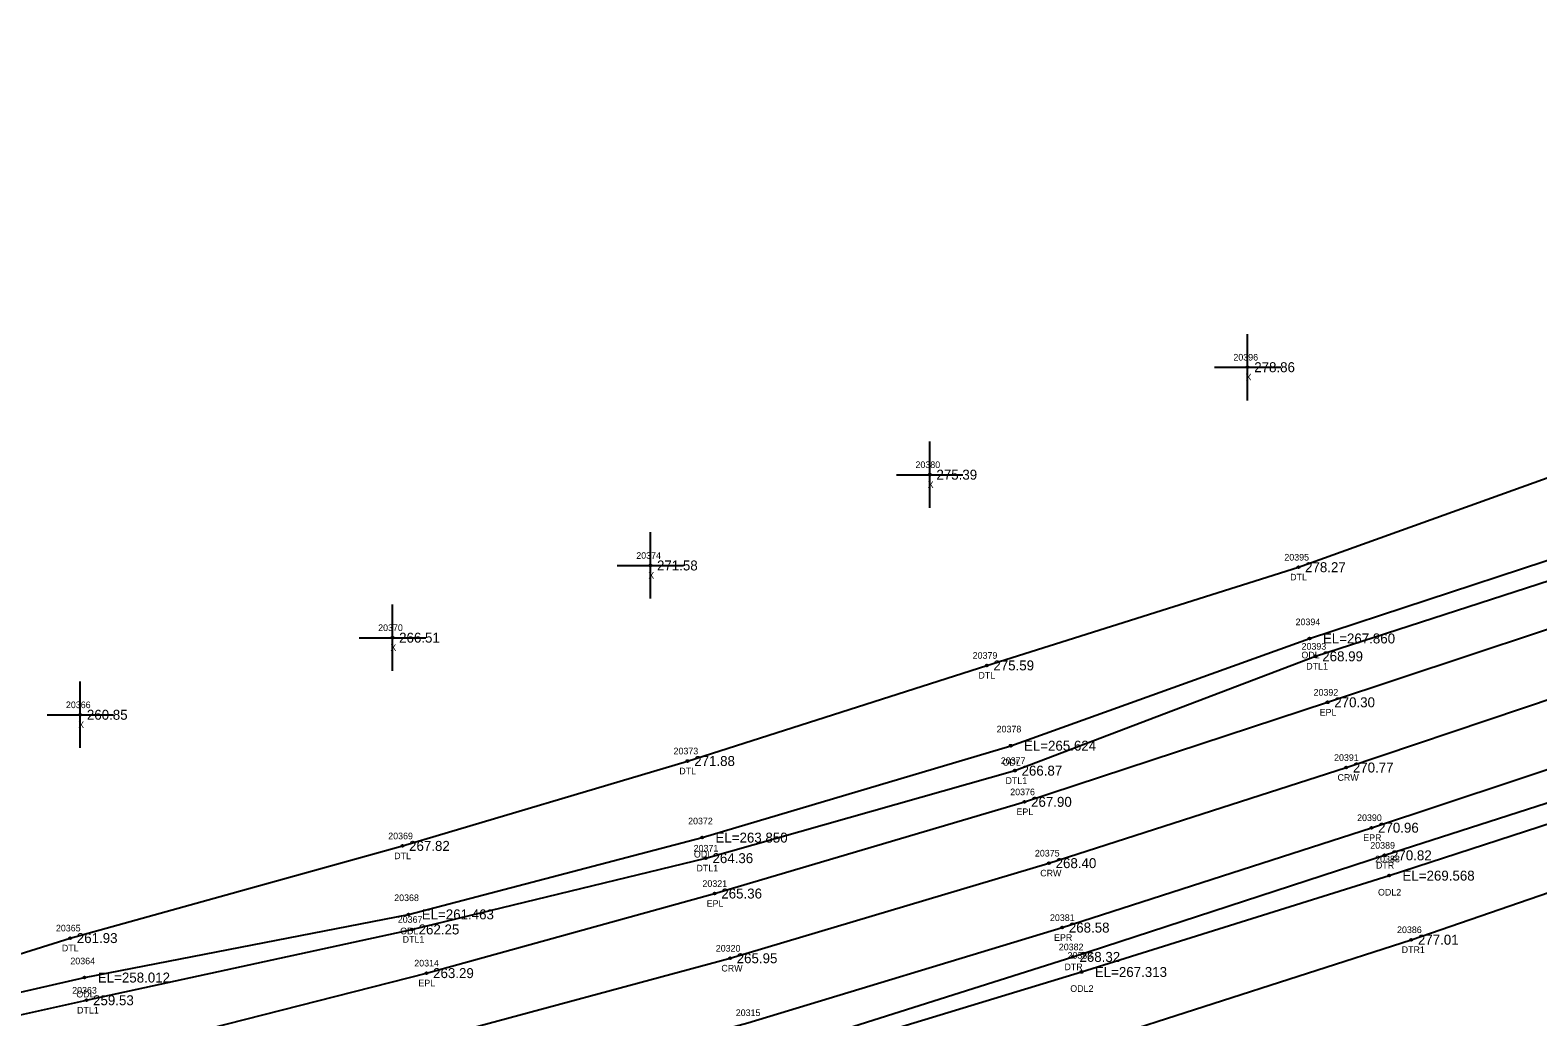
# Model space of a CAD drawing. Extents: x 2275563 to 2277161, y 1075719 to 1076412.
# Drawn here: x 2276701.4 to 2276928.6, y 1076143.1 to 1076291.8 of the extents above; entities that cross this region are included whole.
import ezdxf

# ---------------------------------------------------------------- set-up
doc = ezdxf.new("R2010")
doc.units = 0
for name, color, linetype in [('RD_DTM_BkLn1', 7, 'Continuous'), ('RD_EX_H2O', 7, 'Continuous'), ('RD_EX_H2O_txCode', 7, 'Continuous'), ('RD_EX_Misc', 7, 'Continuous'), ('RD_EX_Misc_txCode', 7, 'Continuous'), ('RD_EX_Road', 7, 'Continuous'), ('RD_EX_Road_txCode', 7, 'Continuous'), ('RD_EX_TX_H2O_ELEV', 7, 'Continuous'), ('RD_EX_TX_Misc_ELEV', 7, 'Continuous'), ('RD_EX_TX_Road_ELEV', 7, 'Continuous'), ('RD_HC_Survey_ELEV', 7, 'Continuous'), ('RD_HC_Survey_txCode', 7, 'Continuous'), ('RD_SMD_Locator', 7, 'Continuous')]:
    doc.layers.add(name, color=color, linetype=linetype)

msp = doc.modelspace()

# ---------------------------------------------------------------- linework, layer by layer
at = {"layer": 'RD_DTM_BkLn1'}
msp.add_lwpolyline([(2276380.47, 1076073.8), (2276432.36, 1076079.4), (2276487.41, 1076086.42), (2276535.62, 1076093.32), (2276578.15, 1076099.97), (2276622.03, 1076107.93), (2276668.51, 1076117.27), (2276714.2, 1076127.81), (2276762.94, 1076140.11), (2276806.88, 1076151.96), (2276854.94, 1076166.29), (2276899.73, 1076180.7), (2276952.88, 1076198.57), (2277000.46, 1076214.72), (2277057.1, 1076234.01), (2277134.93, 1076261.07)], dxfattribs=at)
at = {"layer": 'RD_EX_H2O'}
for points in [[(2276657.47, 1076152.34), (2276661.69, 1076153.68), (2276672.27, 1076150.14), (2276686.1, 1076148.32), (2276707.44, 1076155), (2276757.51, 1076168.89), (2276800.48, 1076181.68), (2276845.56, 1076196.09), (2276892.53, 1076210.89), (2276946.81, 1076230.38), (2276991.46, 1076246.85), (2277048.24, 1076266.02), (2277127.1, 1076291.82)], [(2276657.47, 1076152.34), (2276674.36, 1076145.77), (2276686.08, 1076143.69), (2276709.61, 1076149.05), (2276758.42, 1076158.57), (2276802.68, 1076170.14), (2276849.17, 1076183.99), (2276894.22, 1076200.15), (2276947.41, 1076217.63), (2276994.62, 1076234.82), (2277050.9, 1076254.6), (2277129.78, 1076281.89)], [(2276657.47, 1076152.34), (2276660.53, 1076148.68), (2276675.37, 1076140.15), (2276685.9, 1076140.33), (2276709.89, 1076145.63), (2276758.95, 1076156.3), (2276803.23, 1076167.04), (2276849.8, 1076180.23), (2276895.12, 1076197.46), (2276948.16, 1076214.68), (2276995.02, 1076232.39), (2277051.22, 1076251.9), (2277130.41, 1076279.08)], [(2276577.32, 1076064.99), (2276581.11, 1076068.71), (2276607.06, 1076074.47), (2276628.35, 1076084.13), (2276659.02, 1076095.85), (2276671.39, 1076099.39), (2276718.28, 1076111.88), (2276766.76, 1076124.15), (2276811.4, 1076137.27), (2276858.53, 1076152.16), (2276905.48, 1076167.47), (2276958.61, 1076184.59), (2277007.29, 1076200.4), (2277063.09, 1076219.53), (2277141.85, 1076245.35)], [(2276577.32, 1076064.99), (2276608.07, 1076069.56), (2276629.89, 1076080.39), (2276660.01, 1076094.12), (2276672.11, 1076097.43), (2276718.92, 1076109.66), (2276767.33, 1076122.4), (2276812.13, 1076135.39), (2276859.85, 1076149.89), (2276906.21, 1076164.41), (2276959.66, 1076181.81), (2277008.45, 1076198), (2277064.73, 1076216.97), (2277142.57, 1076243.16)], [(2276577.32, 1076064.99), (2276585.61, 1076060.77), (2276608.72, 1076065.79), (2276630.67, 1076076.21), (2276642.12, 1076079.44), (2276661.39, 1076087.16), (2276674.74, 1076089.6), (2276720.85, 1076101.92), (2276769.56, 1076115.83), (2276815.16, 1076127.06), (2276862.66, 1076139.65), (2276909.53, 1076154.75), (2276961.42, 1076172.61), (2277010.89, 1076191.18), (2277066.25, 1076211.87), (2277143.49, 1076241.1)]]:
    msp.add_lwpolyline(points, dxfattribs=at)
at = {"layer": 'RD_EX_Misc'}
for p, q in [((2276884.87, 1076236.03), (2276884.87, 1076246.03)), ((2276879.87, 1076241.03), (2276889.87, 1076241.03)), ((2276836.98, 1076219.83), (2276836.98, 1076229.83)), ((2276831.98, 1076224.83), (2276841.98, 1076224.83)), ((2276794.87, 1076206.15), (2276794.87, 1076216.15)), ((2276789.87, 1076211.15), (2276799.87, 1076211.15)), ((2276756.01, 1076195.27), (2276756.01, 1076205.27)), ((2276751.01, 1076200.27), (2276761.01, 1076200.27)), ((2276708.96, 1076183.65), (2276708.96, 1076193.65)), ((2276703.96, 1076188.65), (2276713.96, 1076188.65))]:
    msp.add_line(p, q, dxfattribs=at)
at = {"layer": 'RD_EX_Road'}
for points in [[(2276379.21, 1076084.39), (2276432.25, 1076089.28), (2276486.22, 1076095.98), (2276535.61, 1076103.32), (2276577.16, 1076110.11), (2276620.86, 1076117.78), (2276666.21, 1076126.9), (2276712, 1076137.22), (2276761.13, 1076149.72), (2276804.56, 1076161.71), (2276851.24, 1076175.53), (2276896.93, 1076190.53), (2276950.19, 1076208.22), (2276997.45, 1076224.3), (2277053.81, 1076243.77), (2277132.14, 1076270.77)], [(2276381.27, 1076063.04), (2276433.15, 1076069.16), (2276488.59, 1076076.23), (2276537.45, 1076083.34), (2276579.64, 1076090.09), (2276624.07, 1076098.24), (2276670.54, 1076107.46), (2276716.67, 1076118.09), (2276765.18, 1076130.28), (2276809.58, 1076142.25), (2276856.93, 1076156.58), (2276903.53, 1076171.63), (2276957.27, 1076189.46), (2277005.85, 1076206.01), (2277060.98, 1076225.07), (2277139.5, 1076252.36)]]:
    msp.add_lwpolyline(points, dxfattribs=at)
at = {"layer": 'RD_SMD_Locator'}
for centre in [(2276884.87, 1076241.03), (2276836.98, 1076224.83), (2276794.87, 1076211.15), (2276892.53, 1076210.89), (2276756.01, 1076200.27), (2276894.22, 1076200.15), (2276895.12, 1076197.46), (2276845.56, 1076196.09), (2276896.93, 1076190.53), (2276708.96, 1076188.65), (2276849.17, 1076183.99), (2276800.48, 1076181.68), (2276849.8, 1076180.23), (2276899.73, 1076180.7), (2276851.24, 1076175.53), (2276903.53, 1076171.63), (2276757.51, 1076168.89), (2276802.68, 1076170.14), (2276803.23, 1076167.04), (2276905.48, 1076167.47), (2276854.94, 1076166.29), (2276906.21, 1076164.41), (2276804.56, 1076161.71), (2276758.42, 1076158.57), (2276758.95, 1076156.3), (2276856.93, 1076156.58), (2276707.44, 1076155), (2276909.53, 1076154.75), (2276806.88, 1076151.96), (2276858.53, 1076152.16), (2276709.61, 1076149.05), (2276761.13, 1076149.72), (2276859.85, 1076149.89), (2276709.89, 1076145.63)]:
    msp.add_circle(centre, 0.15, dxfattribs=at)

# ---------------------------------------------------------------- texts
at = {"layer": 'RD_EX_H2O_txCode'}
for s, p in [('20395', (2276890.41, 1076211.89)), ('DTL', (2276891.28, 1076208.89)), ('20394', (2276892.1, 1076202.15)), ('20393', (2276893, 1076198.46)), ('20379', (2276843.44, 1076197.09)), ('ODL', (2276892.98, 1076197.15)), ('DTL1', (2276893.71, 1076195.46)), ('DTL', (2276844.31, 1076194.09)), ('20378', (2276847.05, 1076185.99)), ('20373', (2276798.36, 1076182.68)), ('DTL', (2276799.23, 1076179.68)), ('20377', (2276847.68, 1076181.23)), ('ODL', (2276847.93, 1076180.99)), ('DTL1', (2276848.39, 1076178.23)), ('20372', (2276800.56, 1076172.14)), ('20369', (2276755.37, 1076169.89)), ('20371', (2276801.39, 1076168.04)), ('20389', (2276903.36, 1076168.47)), ('DTL', (2276756.27, 1076166.89)), ('ODL', (2276801.43, 1076167.14)), ('20388', (2276904.09, 1076166.41)), ('DTL1', (2276801.82, 1076165.04)), ('DTR', (2276904.21, 1076165.47)), ('ODL2', (2276904.52, 1076161.41)), ('20368', (2276756.27, 1076160.57)), ('20367', (2276756.81, 1076157.3)), ('20365', (2276705.29, 1076156)), ('ODL', (2276757.17, 1076155.57)), ('20386', (2276907.39, 1076155.75)), ('DTL', (2276706.19, 1076153)), ('DTL1', (2276757.54, 1076154.3)), ('20382', (2276856.42, 1076153.16)), ('DTR1', (2276908.09, 1076152.75)), ('20364', (2276707.47, 1076151.05)), ('DTR', (2276857.27, 1076150.16)), ('20383', (2276857.73, 1076151.89)), ('20363', (2276707.74, 1076146.63)), ('ODL', (2276708.37, 1076146.05)), ('ODL2', (2276858.15, 1076146.89)), ('DTL1', (2276708.48, 1076143.63))]:
    msp.add_text(s, height=1, dxfattribs=at).set_placement(p)
at = {"layer": 'RD_EX_Misc_txCode'}
for s, p in [('20396', (2276882.73, 1076242.03)), ('X', (2276884.56, 1076239.03)), ('20380', (2276834.82, 1076225.83)), ('X', (2276836.66, 1076222.83)), ('20374', (2276792.75, 1076212.15)), ('X', (2276794.56, 1076209.15)), ('20370', (2276753.85, 1076201.27)), ('X', (2276755.69, 1076198.27)), ('20366', (2276706.8, 1076189.65)), ('X', (2276708.65, 1076186.65))]:
    msp.add_text(s, height=1, dxfattribs=at).set_placement(p)
at = {"layer": 'RD_EX_Road_txCode'}
for s, p in [('20392', (2276894.81, 1076191.53)), ('EPL', (2276895.73, 1076188.53)), ('20376', (2276849.1, 1076176.53)), ('EPL', (2276850.04, 1076173.53)), ('20390', (2276901.37, 1076172.63)), ('EPR', (2276902.3, 1076169.63)), ('20321', (2276802.72, 1076162.71)), ('EPL', (2276803.35, 1076159.71)), ('20381', (2276855.09, 1076157.58)), ('EPR', (2276855.7, 1076154.58)), ('20314', (2276759.29, 1076150.72)), ('EPL', (2276759.92, 1076147.72)), ('20315', (2276807.74, 1076143.25))]:
    msp.add_text(s, height=1, dxfattribs=at).set_placement(p)
at = {"layer": 'RD_EX_TX_H2O_ELEV'}
for s, p in [('278.27', (2276893.53, 1076210.14)), ('EL=267.860', (2276896.22, 1076199.4)), ('275.59', (2276846.56, 1076195.34)), ('268.99', (2276896.12, 1076196.71)), ('EL=265.624', (2276851.17, 1076183.24)), ('271.88', (2276801.48, 1076180.93)), ('266.87', (2276850.8, 1076179.48)), ('267.82', (2276758.51, 1076168.14)), ('EL=263.850', (2276804.68, 1076169.39)), ('264.36', (2276804.23, 1076166.29)), ('270.82', (2276906.48, 1076166.72)), ('EL=269.568', (2276908.21, 1076163.66)), ('EL=261.463', (2276760.42, 1076157.82)), ('261.93', (2276708.44, 1076154.25)), ('262.25', (2276759.95, 1076155.55)), ('277.01', (2276910.53, 1076154)), ('268.32', (2276859.53, 1076151.41)), ('EL=258.012', (2276711.61, 1076148.3)), ('EL=267.313', (2276861.85, 1076149.14)), ('259.53', (2276710.89, 1076144.88))]:
    msp.add_text(s, height=1.5, dxfattribs=at).set_placement(p)
at = {"layer": 'RD_EX_TX_Misc_ELEV'}
for s, p in [('278.86', (2276885.87, 1076240.28)), ('275.39', (2276837.98, 1076224.08)), ('271.58', (2276795.87, 1076210.4)), ('266.51', (2276757.01, 1076199.52)), ('260.85', (2276709.96, 1076187.9))]:
    msp.add_text(s, height=1.5, dxfattribs=at).set_placement(p)
at = {"layer": 'RD_EX_TX_Road_ELEV'}
for s, p in [('270.30', (2276897.93, 1076189.78)), ('267.90', (2276852.24, 1076174.78)), ('270.96', (2276904.53, 1076170.88)), ('265.36', (2276805.56, 1076160.96)), ('268.58', (2276857.93, 1076155.83)), ('263.29', (2276762.13, 1076148.97))]:
    msp.add_text(s, height=1.5, dxfattribs=at).set_placement(p)
at = {"layer": 'RD_HC_Survey_ELEV'}
for s, p in [('270.77', (2276900.73, 1076179.95)), ('268.40', (2276855.94, 1076165.54)), ('265.95', (2276807.88, 1076151.21))]:
    msp.add_text(s, height=1.5, dxfattribs=at).set_placement(p)
at = {"layer": 'RD_HC_Survey_txCode'}
for s, p in [('20391', (2276897.9, 1076181.7)), ('CRW', (2276898.42, 1076178.7)), ('20375', (2276852.82, 1076167.29)), ('CRW', (2276853.62, 1076164.29)), ('20320', (2276804.73, 1076152.96)), ('CRW', (2276805.57, 1076149.96))]:
    msp.add_text(s, height=1, dxfattribs=at).set_placement(p)

doc.saveas('drawing.dxf')
